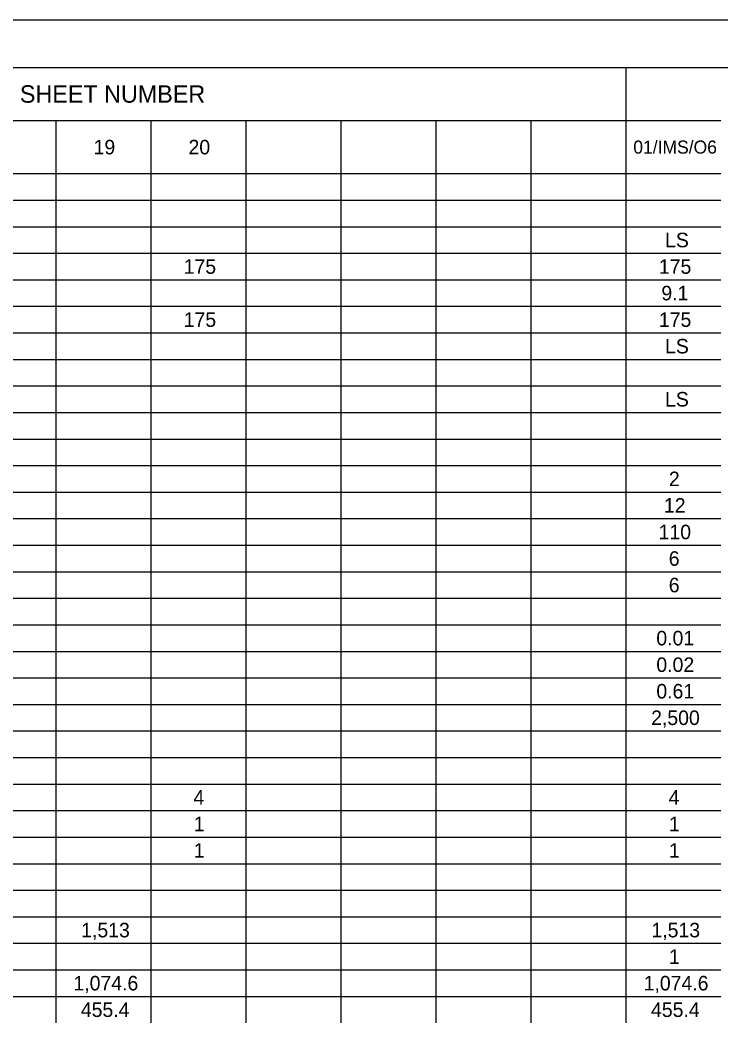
# Model space of a CAD drawing. Extents: x 0 to 34, y 0 to 22.
# Drawn here: x 6.14 to 13.53, y 11.42 to 22 of the extents above; entities that cross this region are included whole.
import ezdxf

# ---------------------------------------------------------------- set-up
doc = ezdxf.new("R2010")
doc.units = 0
for name, color, linetype in [('Default', 7, 'Continuous'), ('SH_Border', 7, 'Continuous'), ('SH_Cut_Line', 7, 'Continuous')]:
    doc.layers.add(name, color=color, linetype=linetype)

msp = doc.modelspace()

# ---------------------------------------------------------------- linework, layer by layer
at = {"layer": 'Default'}
for p, q in [((1.5, 21.5), (6.513, 21.5)), ((6.513, 21.5), (7.515, 21.5)), ((7.515, 21.5), (12.528, 21.5)), ((12.528, 21.5), (13.53, 21.5)), ((12.528, 21.5), (12.528, 21.22)), ((12.528, 21.22), (12.528, 20.94)), ((1.5, 20.94), (6.513, 20.94)), ((6.513, 20.94), (7.515, 20.94)), ((6.513, 20.94), (6.513, 20.66)), ((7.515, 20.94), (12.528, 20.94)), ((7.515, 20.94), (7.515, 20.66)), ((8.518, 20.94), (8.518, 20.66)), ((9.52, 20.94), (9.52, 20.66)), ((10.523, 20.94), (10.523, 20.66)), ((11.525, 20.94), (11.525, 20.66)), ((12.528, 20.94), (13.53, 20.94)), ((12.528, 20.94), (12.528, 20.66)), ((6.513, 20.66), (6.513, 20.38)), ((7.515, 20.66), (7.515, 20.38)), ((8.518, 20.66), (8.518, 20.38)), ((9.52, 20.66), (9.52, 20.38)), ((10.523, 20.66), (10.523, 20.38)), ((11.525, 20.66), (11.525, 20.38)), ((12.528, 20.66), (12.528, 20.38)), ((1.5, 20.38), (6.513, 20.38)), ((6.513, 20.38), (7.515, 20.38)), ((6.513, 20.38), (6.513, 20.1)), ((7.515, 20.38), (12.528, 20.38)), ((7.515, 20.38), (7.515, 20.1)), ((8.518, 20.38), (8.518, 20.1)), ((9.52, 20.38), (9.52, 20.1)), ((10.523, 20.38), (10.523, 20.1)), ((11.525, 20.38), (11.525, 20.1)), ((12.528, 20.38), (13.53, 20.38)), ((12.528, 20.38), (12.528, 20.1)), ((1.5, 20.1), (6.513, 20.1)), ((6.513, 20.1), (7.515, 20.1)), ((6.513, 20.1), (6.513, 18.7)), ((7.515, 20.1), (12.528, 20.1)), ((7.515, 20.1), (7.515, 18.7)), ((8.518, 20.1), (8.518, 18.7)), ((9.52, 20.1), (9.52, 18.7)), ((10.523, 20.1), (10.523, 18.7)), ((11.525, 20.1), (11.525, 18.7)), ((12.528, 20.1), (13.53, 20.1)), ((12.528, 20.1), (12.528, 18.7)), ((1.5, 19.82), (6.513, 19.82)), ((6.513, 19.82), (7.515, 19.82)), ((7.515, 19.82), (12.528, 19.82)), ((12.528, 19.82), (13.53, 19.82)), ((1.5, 19.54), (6.513, 19.54)), ((6.513, 19.54), (7.515, 19.54)), ((7.515, 19.54), (12.528, 19.54)), ((12.528, 19.54), (13.53, 19.54)), ((1.5, 19.26), (6.513, 19.26)), ((6.513, 19.26), (7.515, 19.26)), ((7.515, 19.26), (12.528, 19.26)), ((12.528, 19.26), (13.53, 19.26)), ((1.5, 18.98), (6.513, 18.98)), ((6.513, 18.98), (7.515, 18.98)), ((7.515, 18.98), (12.528, 18.98)), ((12.528, 18.98), (13.53, 18.98)), ((1.5, 18.7), (6.513, 18.7)), ((6.513, 18.7), (7.515, 18.7)), ((6.513, 18.7), (6.513, 18.14)), ((7.515, 18.7), (12.528, 18.7)), ((7.515, 18.7), (7.515, 18.14)), ((8.518, 18.7), (8.518, 18.14)), ((9.52, 18.7), (9.52, 18.14)), ((10.523, 18.7), (10.523, 18.14)), ((11.525, 18.7), (11.525, 18.14)), ((12.528, 18.7), (13.53, 18.7)), ((12.528, 18.7), (12.528, 18.14)), ((1.5, 18.42), (6.513, 18.42)), ((6.513, 18.42), (7.515, 18.42)), ((7.515, 18.42), (12.528, 18.42)), ((12.528, 18.42), (13.53, 18.42)), ((1.5, 18.14), (6.513, 18.14)), ((6.513, 18.14), (7.515, 18.14)), ((6.513, 18.14), (6.513, 17.86)), ((7.515, 18.14), (12.528, 18.14)), ((7.515, 18.14), (7.515, 17.86)), ((8.518, 18.14), (8.518, 17.86)), ((9.52, 18.14), (9.52, 17.86)), ((10.523, 18.14), (10.523, 17.86)), ((11.525, 18.14), (11.525, 17.86)), ((12.528, 18.14), (13.53, 18.14)), ((12.528, 18.14), (12.528, 17.86)), ((1.5, 17.86), (6.513, 17.86)), ((6.513, 17.86), (7.515, 17.86)), ((6.513, 17.86), (6.513, 17.58)), ((7.515, 17.86), (12.528, 17.86)), ((7.515, 17.86), (7.515, 17.58)), ((8.518, 17.86), (8.518, 17.58)), ((9.52, 17.86), (9.52, 17.58)), ((10.523, 17.86), (10.523, 17.58)), ((11.525, 17.86), (11.525, 17.58)), ((12.528, 17.86), (13.53, 17.86)), ((12.528, 17.86), (12.528, 17.58)), ((1.5, 17.58), (6.513, 17.58)), ((6.513, 17.58), (7.515, 17.58)), ((6.513, 17.58), (6.513, 17.3)), ((7.515, 17.58), (12.528, 17.58)), ((7.515, 17.58), (7.515, 17.3)), ((8.518, 17.58), (8.518, 17.3)), ((9.52, 17.58), (9.52, 17.3)), ((10.523, 17.58), (10.523, 17.3)), ((11.525, 17.58), (11.525, 17.3)), ((12.528, 17.58), (13.53, 17.58)), ((12.528, 17.58), (12.528, 17.3)), ((1.5, 17.3), (6.513, 17.3)), ((6.513, 17.3), (7.515, 17.3)), ((6.513, 17.3), (6.513, 17.02)), ((7.515, 17.3), (12.528, 17.3)), ((7.515, 17.3), (7.515, 17.02)), ((8.518, 17.3), (8.518, 17.02)), ((9.52, 17.3), (9.52, 17.02)), ((10.523, 17.3), (10.523, 17.02)), ((11.525, 17.3), (11.525, 17.02)), ((12.528, 17.3), (13.53, 17.3)), ((12.528, 17.3), (12.528, 17.02)), ((1.5, 17.02), (6.513, 17.02)), ((6.513, 17.02), (7.515, 17.02)), ((6.513, 17.02), (6.513, 16.74)), ((7.515, 17.02), (12.528, 17.02)), ((7.515, 17.02), (7.515, 16.74)), ((8.518, 17.02), (8.518, 16.74)), ((9.52, 17.02), (9.52, 16.74)), ((10.523, 17.02), (10.523, 16.74)), ((11.525, 17.02), (11.525, 16.74)), ((12.528, 17.02), (13.53, 17.02)), ((12.528, 17.02), (12.528, 16.74)), ((1.5, 16.74), (6.513, 16.74)), ((6.513, 16.74), (7.515, 16.74)), ((6.513, 16.74), (6.513, 16.18)), ((7.515, 16.74), (12.528, 16.74)), ((7.515, 16.74), (7.515, 16.18)), ((8.518, 16.74), (8.518, 16.18)), ((9.52, 16.74), (9.52, 16.18)), ((10.523, 16.74), (10.523, 16.18)), ((11.525, 16.74), (11.525, 16.18)), ((12.528, 16.74), (13.53, 16.74)), ((12.528, 16.74), (12.528, 16.18)), ((1.5, 16.46), (6.513, 16.46)), ((6.513, 16.46), (7.515, 16.46)), ((7.515, 16.46), (12.528, 16.46)), ((12.528, 16.46), (13.53, 16.46)), ((1.5, 16.18), (6.513, 16.18)), ((6.513, 16.18), (7.515, 16.18)), ((6.513, 16.18), (6.513, 15.9)), ((7.515, 16.18), (12.528, 16.18)), ((7.515, 16.18), (7.515, 15.9)), ((8.518, 16.18), (8.518, 15.9)), ((9.52, 16.18), (9.52, 15.9)), ((10.523, 16.18), (10.523, 15.9)), ((11.525, 16.18), (11.525, 15.9)), ((12.528, 16.18), (13.53, 16.18)), ((12.528, 16.18), (12.528, 15.9)), ((1.5, 15.9), (6.513, 15.9)), ((6.513, 15.9), (7.515, 15.9)), ((6.513, 15.9), (6.513, 15.62)), ((7.515, 15.9), (12.528, 15.9)), ((7.515, 15.9), (7.515, 15.62)), ((8.518, 15.9), (8.518, 15.62)), ((9.52, 15.9), (9.52, 15.62)), ((10.523, 15.9), (10.523, 15.62)), ((11.525, 15.9), (11.525, 15.62)), ((12.528, 15.9), (13.53, 15.9)), ((12.528, 15.9), (12.528, 15.62)), ((1.5, 15.62), (6.513, 15.62)), ((6.513, 15.62), (7.515, 15.62)), ((6.513, 15.62), (6.513, 15.34)), ((7.515, 15.62), (12.528, 15.62)), ((7.515, 15.62), (7.515, 15.34)), ((8.518, 15.62), (8.518, 15.34)), ((9.52, 15.62), (9.52, 15.34)), ((10.523, 15.62), (10.523, 15.34)), ((11.525, 15.62), (11.525, 15.34)), ((12.528, 15.62), (13.53, 15.62)), ((12.528, 15.62), (12.528, 15.34)), ((1.5, 15.34), (6.513, 15.34)), ((6.513, 15.34), (7.515, 15.34)), ((6.513, 15.34), (6.513, 14.78)), ((7.515, 15.34), (12.528, 15.34)), ((7.515, 15.34), (7.515, 14.78)), ((8.518, 15.34), (8.518, 14.78)), ((9.52, 15.34), (9.52, 14.78)), ((10.523, 15.34), (10.523, 14.78)), ((11.525, 15.34), (11.525, 14.78)), ((12.528, 15.34), (13.53, 15.34)), ((12.528, 15.34), (12.528, 14.78)), ((1.5, 15.06), (6.513, 15.06)), ((6.513, 15.06), (7.515, 15.06)), ((7.515, 15.06), (12.528, 15.06)), ((12.528, 15.06), (13.53, 15.06)), ((1.5, 14.78), (6.513, 14.78)), ((6.513, 14.78), (7.515, 14.78)), ((6.513, 14.78), (6.513, 14.5)), ((7.515, 14.78), (12.528, 14.78)), ((7.515, 14.78), (7.515, 14.5)), ((8.518, 14.78), (8.518, 14.5)), ((9.52, 14.78), (9.52, 14.5)), ((10.523, 14.78), (10.523, 14.5)), ((11.525, 14.78), (11.525, 14.5)), ((12.528, 14.78), (13.53, 14.78)), ((12.528, 14.78), (12.528, 14.5)), ((1.5, 14.5), (6.513, 14.5)), ((6.513, 14.5), (7.515, 14.5)), ((6.513, 14.5), (6.513, 14.22)), ((7.515, 14.5), (12.528, 14.5)), ((7.515, 14.5), (7.515, 14.22)), ((8.518, 14.5), (8.518, 14.22)), ((9.52, 14.5), (9.52, 14.22)), ((10.523, 14.5), (10.523, 14.22)), ((11.525, 14.5), (11.525, 14.22)), ((12.528, 14.5), (13.53, 14.5)), ((12.528, 14.5), (12.528, 14.22)), ((1.5, 14.22), (6.513, 14.22)), ((6.513, 14.22), (7.515, 14.22)), ((6.513, 14.22), (6.513, 13.94)), ((7.515, 14.22), (12.528, 14.22)), ((7.515, 14.22), (7.515, 13.94)), ((8.518, 14.22), (8.518, 13.94)), ((9.52, 14.22), (9.52, 13.94)), ((10.523, 14.22), (10.523, 13.94)), ((11.525, 14.22), (11.525, 13.94)), ((12.528, 14.22), (13.53, 14.22)), ((12.528, 14.22), (12.528, 13.94)), ((1.5, 13.94), (6.513, 13.94)), ((6.513, 13.94), (7.515, 13.94)), ((6.513, 13.94), (6.513, 11.7)), ((7.515, 13.94), (12.528, 13.94)), ((7.515, 13.94), (7.515, 11.7)), ((8.518, 13.94), (8.518, 11.7)), ((9.52, 13.94), (9.52, 11.7)), ((10.523, 13.94), (10.523, 11.7)), ((11.525, 13.94), (11.525, 11.7)), ((12.528, 13.94), (13.53, 13.94)), ((12.528, 13.94), (12.528, 11.7)), ((1.5, 13.66), (6.513, 13.66)), ((6.513, 13.66), (7.515, 13.66)), ((7.515, 13.66), (12.528, 13.66)), ((12.528, 13.66), (13.53, 13.66)), ((1.5, 13.38), (6.513, 13.38)), ((6.513, 13.38), (7.515, 13.38)), ((7.515, 13.38), (12.528, 13.38)), ((12.528, 13.38), (13.53, 13.38)), ((1.5, 13.1), (6.513, 13.1)), ((6.513, 13.1), (7.515, 13.1)), ((7.515, 13.1), (12.528, 13.1)), ((12.528, 13.1), (13.53, 13.1)), ((1.5, 12.82), (6.513, 12.82)), ((6.513, 12.82), (7.515, 12.82)), ((7.515, 12.82), (12.528, 12.82)), ((12.528, 12.82), (13.53, 12.82)), ((1.5, 12.54), (6.513, 12.54)), ((6.513, 12.54), (7.515, 12.54)), ((7.515, 12.54), (12.528, 12.54)), ((12.528, 12.54), (13.53, 12.54)), ((1.5, 12.26), (6.513, 12.26)), ((6.513, 12.26), (7.515, 12.26)), ((7.515, 12.26), (12.528, 12.26)), ((12.528, 12.26), (13.53, 12.26)), ((1.5, 11.98), (6.513, 11.98)), ((6.513, 11.98), (7.515, 11.98)), ((7.515, 11.98), (12.528, 11.98)), ((12.528, 11.98), (13.53, 11.98)), ((1.5, 11.7), (6.513, 11.7)), ((6.513, 11.7), (7.515, 11.7)), ((6.513, 11.7), (6.513, 11.42)), ((7.515, 11.7), (12.528, 11.7)), ((7.515, 11.7), (7.515, 11.42)), ((8.518, 11.7), (8.518, 11.42)), ((9.52, 11.7), (9.52, 11.42)), ((10.523, 11.7), (10.523, 11.42)), ((11.525, 11.7), (11.525, 11.42)), ((12.528, 11.7), (13.53, 11.7)), ((12.528, 11.7), (12.528, 11.42))]:
    msp.add_line(p, q, dxfattribs=at)
at = {"layer": 'SH_Border'}
msp.add_lwpolyline([(1.5, 21.5), (33.5, 21.5), (33.5, 0.5), (1.5, 0.5)], close=True, dxfattribs=at)
at = {"layer": 'SH_Cut_Line'}
msp.add_lwpolyline([(0, 0), (34, 0), (34, 22), (0, 22)], close=True, dxfattribs=at)

# ---------------------------------------------------------------- texts
at = {"layer": 'Default'}
for s, height, p in [('SHEET NUMBER', 0.184, (6.135, 21.128)), ('19', 0.1533, (6.913, 20.583)), ('20', 0.1533, (7.914, 20.583)), ('01/IMS/O6', 0.138, (12.606, 20.591)), ('LS', 0.1533, (12.941, 19.603)), ('175', 0.1533, (7.863, 19.323)), ('175', 0.1533, (12.876, 19.323)), ('9.1', 0.1533, (12.902, 19.043)), ('175', 0.1533, (7.863, 18.763)), ('175', 0.1533, (12.876, 18.763)), ('LS', 0.1533, (12.941, 18.483)), ('LS', 0.1533, (12.941, 17.923)), ('2', 0.153, (12.982, 17.083)), ('12', 0.1533, (12.929, 16.803)), ('110', 0.1533, (12.873, 16.523)), ('6', 0.153, (12.98, 16.243)), ('6', 0.153, (12.98, 15.963)), ('0.01', 0.1533, (12.849, 15.403)), ('0.02', 0.1533, (12.849, 15.123)), ('0.61', 0.1533, (12.849, 14.843)), ('2,500', 0.1533, (12.794, 14.563)), ('4', 0.153, (7.966, 13.723)), ('4', 0.153, (12.979, 13.723)), ('1', 0.153, (7.969, 13.443)), ('1', 0.153, (12.982, 13.443)), ('1', 0.153, (7.969, 13.163)), ('1', 0.153, (12.982, 13.163)), ('1,513', 0.1533, (6.782, 12.323)), ('1,513', 0.1533, (12.797, 12.323)), ('1', 0.153, (12.982, 12.043)), ('1,074.6', 0.1533, (6.7, 11.763)), ('1,074.6', 0.1533, (12.715, 11.763)), ('455.4', 0.1533, (6.778, 11.483)), ('455.4', 0.1533, (12.793, 11.483))]:
    msp.add_text(s, height=height, dxfattribs=at).set_placement(p)

doc.saveas('drawing.dxf')
